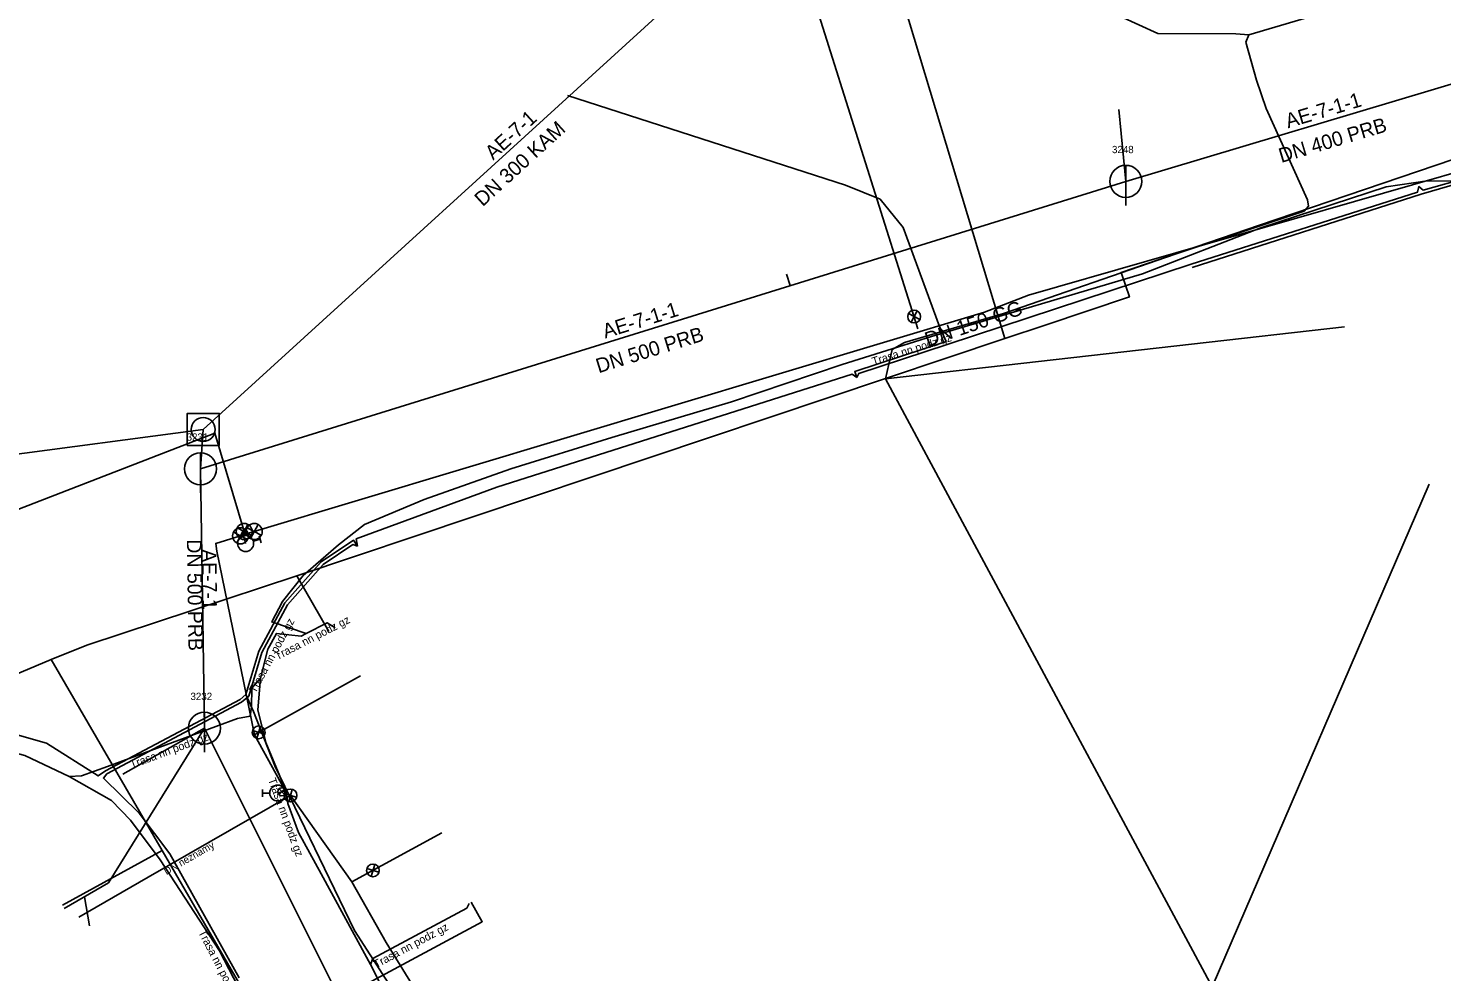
# Model space of a CAD drawing. Extents: x -493753 to -49291, y -1127285 to -112662.
# Drawn here: x -493312 to -493223.7, y -1127083.7 to -1127024.8 of the extents above; entities that cross this region are included whole.
import ezdxf

# ---------------------------------------------------------------- set-up
doc = ezdxf.new("R2010")
doc.units = 0
for name, color, linetype in [('Vrstva 1', 7, 'Continuous'), ('Vrstva 14', 7, 'Continuous'), ('Vrstva 15', 7, 'Continuous'), ('Vrstva 17', 7, 'Continuous'), ('Vrstva 19', 7, 'Continuous'), ('Vrstva 20', 7, 'Continuous'), ('Vrstva 22', 7, 'Continuous'), ('Vrstva 24', 7, 'Continuous'), ('Vrstva 25', 7, 'Continuous'), ('Vrstva 26', 7, 'Continuous'), ('Vrstva 28', 7, 'Continuous'), ('Vrstva 39', 7, 'Continuous'), ('Vrstva 5', 7, 'Continuous'), ('Vrstva 9', 7, 'Continuous')]:
    doc.layers.add(name, color=color, linetype=linetype)

# ---------------------------------------------------------------- blocks, each defined once
blk = doc.blocks.new('MOSYM1')
at = {"layer": 'Vrstva 1'}
blk.add_lwpolyline([(-0.05, -0.05), (0.05, -0.05), (0.05, 0.05), (-0.05, 0.05), (-0.05, -0.05)], dxfattribs=at)
blk.add_circle((0, 0), 0.0375, dxfattribs=at)
blk = doc.blocks.new('_UZAVE')
at = {"layer": 'Vrstva 1'}
for p, q in [((-0.035, -0.035), (0.035, 0.035)), ((0.035, -0.035), (-0.035, 0.035))]:
    blk.add_line(p, q, dxfattribs=at)
for radius in [0.05, 0.0025]:
    blk.add_circle((0, 0), radius, dxfattribs=at)
blk = doc.blocks.new('_UZAV0')
at = {"layer": 'Vrstva 1'}
for p, q in [((-0.035, -0.035), (0.035, 0.035)), ((0.035, -0.035), (-0.035, 0.035))]:
    blk.add_line(p, q, dxfattribs=at)
for radius in [0.05, 0.0025]:
    blk.add_circle((0, 0), radius, dxfattribs=at)
blk = doc.blocks.new('_HYDRA')
at = {"layer": 'Vrstva 1'}
for p, q in [((-0.0225, 0.095), (0.0225, 0.095)), ((0, 0.095), (0, 0.05))]:
    blk.add_line(p, q, dxfattribs=at)
blk.add_circle((0, 0), 0.05, dxfattribs=at)
blk = doc.blocks.new('_SACH0')
at = {"layer": 'Vrstva 1'}
blk.add_line((0, 0.05), (0, -0.075), dxfattribs=at)
blk.add_circle((0, 0), 0.05, dxfattribs=at)

msp = doc.modelspace()

# ---------------------------------------------------------------- linework, layer by layer
at = {"layer": 'Vrstva 1'}
for p, q in [((-493295.19, -1127058.95), (-493293.19, -1127062.42)), ((-493308.31, -1127063.27), (-493310.54, -1127064.17)), ((-493303.61, -1127076.09), (-493309.83, -1127079.5))]:
    msp.add_line(p, q, dxfattribs=at)
for points in [[(-493250.96, -1127044.13), (-493264.29, -1127000), (-493267.86, -1126988.17), (-493270.15, -1126981.69)], [(-493211.21, -1127031.6), (-493221.15, -1127034.33), (-493221.76, -1127032.53), (-493224.08, -1127033.32), (-493235.06, -1127037.06), (-493243.7, -1127040), (-493243.18, -1127041.53), (-493248.45, -1127043.29), (-493250.96, -1127044.13), (-493295.19, -1127058.95), (-493308.31, -1127063.27)], [(-493344.2, -1127078.27), (-493319.39, -1127067.89), (-493310.54, -1127064.17)], [(-493310.54, -1127064.17), (-493303.61, -1127076.09), (-493297.49, -1127086.65), (-493292.63, -1127095.05), (-493290.18, -1127099.28), (-493289.82, -1127099.92), (-493284.29, -1127109.66), (-493280.22, -1127116.82), (-493273.01, -1127129.21), (-493269.95, -1127134.48), (-493269.4, -1127135.43), (-493265.789, -1127142.323)], [(-493297.49, -1127086.65), (-493295.74, -1127087.06), (-493283.61, -1127080.54), (-493284.31, -1127079.33)]]:
    msp.add_lwpolyline(points, dxfattribs=at)
at = {"layer": 'Vrstva 14'}
for points in [[(-493258.41, -1127046.65), (-493229.74, -1127043.4)], [(-493238.01, -1127084.61), (-493258.41, -1127046.65)], [(-493238.01, -1127084.61), (-493224.45, -1127053.23)]]:
    msp.add_lwpolyline(points, dxfattribs=at)
at = {"layer": 'Vrstva 15'}
for p, q in [((-493301.04, -1127049.81), (-493263.8, -1127015.89)), ((-493215.87, -1127026.1), (-493243.41, -1127034.33)), ((-493243.84, -1127029.84), (-493243.41, -1127034.32)), ((-493243.41, -1127034.33), (-493301.21, -1127052.27)), ((-493264.61, -1127040.11), (-493264.38, -1127040.83)), ((-493332.87, -1127054), (-493301.04, -1127049.81)), ((-493301.21, -1127052.27), (-493301.04, -1127049.81)), ((-493300.97, -1127068.46), (-493301.21, -1127052.27)), ((-493306.06, -1127071.32), (-493300.97, -1127068.46)), ((-493280.38, -1127109.5), (-493300.97, -1127068.46)), ((-493308.14, -1127080.8), (-493308.46, -1127078.98))]:
    msp.add_line(p, q, dxfattribs=at)
msp.add_lwpolyline([(-493309.72, -1127079.71), (-493306.95, -1127078.11), (-493300.97, -1127068.46)], dxfattribs=at)
at = {"layer": 'Vrstva 20'}
for p, q in [((-493256.39, -1127043.53), (-493274.59, -1126985.82)), ((-493298.42, -1127056.37), (-493298.48, -1127056.18)), ((-493298.42, -1127056.37), (-493298.71, -1127056.45)), ((-493298.39, -1127056.93), (-493298.52, -1127056.4)), ((-493295.59, -1127072.66), (-493304.48, -1127077.77)), ((-493286.13, -1127075), (-493291.75, -1127078.05)), ((-493304.48, -1127077.77), (-493308.81, -1127080.25))]:
    msp.add_line(p, q, dxfattribs=at)
for points in [[(-493298.48, -1127056.18), (-493300.31, -1127050.04), (-493321.24, -1127058.14), (-493355.65, -1127071.3), (-493365, -1127074.9), (-493368.31, -1127076.35), (-493386.57, -1127054.09), (-493416.18, -1127013.57), (-493425.33, -1127000), (-493450.1, -1126961.95), (-493457.06, -1126948.64)], [(-493219.05, -1127032.65), (-493219.91, -1127032.94), (-493249.48, -1127041.42), (-493252.24, -1127042.48), (-493297.85, -1127056.18)], [(-493297.85, -1127056.18), (-493298.14, -1127056.27), (-493298.42, -1127056.37)], [(-493298.71, -1127056.45), (-493300.26, -1127056.92), (-493300.18, -1127057.4), (-493297.84, -1127068.87), (-493295.92, -1127072.34), (-493295.59, -1127072.66), (-493291.75, -1127078.05), (-493289.61, -1127081.83), (-493285.88, -1127087.87), (-493285.64, -1127088.31), (-493284.46, -1127091.33), (-493277.34, -1127105.5), (-493273.67, -1127111.53), (-493268.24, -1127121.11), (-493263.75, -1127129.69), (-493262.62, -1127131.58), (-493258.641, -1127138.619)], [(-493291.21, -1127065.2), (-493297.58, -1127068.72), (-493297.84, -1127068.87)], [(-493295.92, -1127072.34), (-493296.13, -1127072.43), (-493296.38, -1127072.51)]]:
    msp.add_lwpolyline(points, dxfattribs=at)
at = {"layer": 'Vrstva 25'}
for points in [[(-493260.22, -1127046.57), (-493260.34, -1127046.2), (-493254.63, -1127044.32), (-493255.05, -1127043.39), (-493257.32, -1127037.21), (-493258.76, -1127035.43), (-493260.92, -1127034.55), (-493278.28, -1127028.96)], [(-493260.22, -1127046.57), (-493260.09, -1127046.32), (-493254.57, -1127044.51), (-493239.33, -1127039.5), (-493225.18, -1127034.99), (-493225.11, -1127034.65), (-493224.84, -1127034.88), (-493222.03, -1127034.07), (-493217.89, -1127035.04), (-493215.41, -1127036.97), (-493213.7, -1127040.65), (-493212.86, -1127040.33), (-493206.46, -1127037.45), (-493205.76, -1127037.19), (-493205.83, -1127035.11), (-493205.49, -1127032.1), (-493204.16, -1127029.47), (-493203.78, -1127030.01)], [(-493203.78, -1127030.01), (-493204.09, -1127029.77), (-493205.29, -1127032.16), (-493205.63, -1127035.12), (-493205.56, -1127037.33), (-493206.38, -1127037.63), (-493212.78, -1127040.51), (-493213.8, -1127040.9), (-493215.57, -1127037.09), (-493217.97, -1127035.22), (-493222.03, -1127034.27), (-493224.95, -1127035.12), (-493239.27, -1127039.69)], [(-493260.22, -1127046.57), (-493260.5, -1127046.35), (-493282.7, -1127053.42), (-493291.48, -1127056.64), (-493291.4, -1127057.09)], [(-493291.4, -1127057.09), (-493291.65, -1127056.73), (-493293.68, -1127058.08), (-493295.94, -1127060.63), (-493297.56, -1127063.66), (-493298.37, -1127066.35), (-493298.73, -1127066.66), (-493307.14, -1127071.12), (-493307.61, -1127071.44), (-493310.84, -1127069.4), (-493314.8, -1127068.28), (-493317.63, -1127068.47), (-493317.86, -1127068.21)], [(-493298.8, -1127084.04), (-493303.13, -1127076.31), (-493305.04, -1127073.77), (-493307.27, -1127071.57), (-493307.06, -1127071.3), (-493298.65, -1127066.84), (-493298.19, -1127066.46), (-493297.37, -1127063.74), (-493295.77, -1127060.75), (-493293.55, -1127058.23), (-493291.7, -1127057), (-493291.4, -1127057.09)]]:
    msp.add_lwpolyline(points, dxfattribs=at)
at = {"layer": 'Vrstva 26'}
for p, q in [((-493298.37, -1127066.35), (-493297.89, -1127067.41)), ((-493297.89, -1127067.41), (-493296.57, -1127070.81)), ((-493296.57, -1127070.81), (-493291.59, -1127081.08)), ((-493291.59, -1127081.08), (-493288.11, -1127086.48))]:
    msp.add_line(p, q, dxfattribs=at)
at = {"layer": 'Vrstva 39'}
for points in [[(-493235.73, -1127025.17), (-493236.53, -1127025.12), (-493241.4, -1127025.09), (-493243.79, -1127024), (-493248.52, -1127013.69), (-493250.11, -1127006.96), (-493251.66, -1127001.72), (-493252.99, -1126995.77), (-493253.77, -1126987.81), (-493254.97, -1126977.02), (-493255.48, -1126962.33), (-493256.31, -1126954.12), (-493256.68, -1126945.15), (-493257.3, -1126943.45), (-493260.26, -1126941.69), (-493266.63, -1126938.06), (-493269.86, -1126938.09), (-493289.32, -1126944.6), (-493307.43, -1126950.45), (-493319.46, -1126954.73), (-493321.82, -1126955.73), (-493322.21, -1126955.38)], [(-493235.73, -1127025.17), (-493229.59, -1127023.36), (-493217.62, -1127019.87), (-493209.8, -1127017.48), (-493201.12, -1127014.06), (-493191.79, -1127010.53), (-493180.27, -1127008.11), (-493179.99, -1127008.93), (-493179.17, -1127010.93), (-493177.18, -1127016.55), (-493176.51, -1127018.4), (-493171.32, -1127029.71), (-493169.32, -1127034.4), (-493165.23, -1127043.1), (-493161.92, -1127050.08), (-493161.26, -1127050.88)], [(-493258.41, -1127046.65), (-493258, -1127044.82), (-493257.23, -1127044.38), (-493251.05, -1127042.58), (-493240.33, -1127038.87), (-493232.27, -1127036.18), (-493231.99, -1127035.87), (-493232.06, -1127035.48), (-493234.63, -1127029.78), (-493235.25, -1127028.01), (-493235.92, -1127025.62), (-493235.73, -1127025.17)]]:
    msp.add_lwpolyline(points, dxfattribs=at)
at = {"layer": 'Vrstva 5'}
for points in [[(-493294.6, -1127062.55), (-493296.76, -1127061.82), (-493296.08, -1127060.54), (-493294.79, -1127058.92), (-493292.58, -1127057.01), (-493290.97, -1127055.75), (-493287.24, -1127054.18), (-493281.83, -1127052.27), (-493275.52, -1127050.32), (-493268.05, -1127048.08), (-493261.13, -1127045.75), (-493255.54, -1127044), (-493242.37, -1127040.1), (-493234.97, -1127037.22), (-493227.14, -1127034.67), (-493224.59, -1127034.28), (-493222.11, -1127034.31), (-493219.35, -1127035.1), (-493217.51, -1127035.69), (-493216.02, -1127036.75), (-493214.15, -1127038.64), (-493213.79, -1127039.43), (-493213.44, -1127041.17)], [(-493294.6, -1127062.55), (-493293.29, -1127061.88), (-493292.8, -1127062.19)], [(-493294.6, -1127062.55), (-493294.93, -1127062.72), (-493296.47, -1127062.54), (-493297, -1127063.52), (-493297.46, -1127065.33)], [(-493297.46, -1127065.33), (-493298.01, -1127065.97), (-493298.03, -1127067.13), (-493298.11, -1127067.7), (-493298.89, -1127067.85), (-493307.03, -1127070.85), (-493308.65, -1127071.43), (-493309.42, -1127071.48)], [(-493290.59, -1127083.21), (-493290.84, -1127082.76), (-493293.67, -1127077.56), (-493295.09, -1127074.98), (-493295.76, -1127073.16), (-493295.88, -1127072.35), (-493297.13, -1127069.35), (-493297.63, -1127067.32), (-493297.46, -1127065.33)], [(-493309.42, -1127071.48), (-493312.18, -1127070.17), (-493314.91, -1127069.46), (-493317.14, -1127069.17), (-493318.88, -1127069.38), (-493323.79, -1127070.46), (-493330.76, -1127073.17), (-493334.55, -1127075.03), (-493338.89, -1127076.91), (-493343.3, -1127078.76), (-493344.09, -1127079.15), (-493345.41, -1127079.25)], [(-493291.68, -1127098.47), (-493292.92, -1127096.12), (-493296.27, -1127089.59), (-493300.03, -1127082.35), (-493303.74, -1127076.68), (-493305.59, -1127074.21), (-493306.76, -1127072.98), (-493309.42, -1127071.48)], [(-493290.59, -1127083.21), (-493290.44, -1127082.84), (-493284.58, -1127079.7), (-493284.42, -1127079.4)], [(-493284.76, -1127093.64), (-493284.99, -1127093.23), (-493288.82, -1127086.72), (-493290.59, -1127083.21)]]:
    msp.add_lwpolyline(points, dxfattribs=at)

# ---------------------------------------------------------------- block references
at = {"layer": 'Vrstva 17', "xscale": 19.997500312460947, "yscale": 19.997500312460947}
for p in [(-493243.41, -1127034.32), (-493301.21, -1127052.27), (-493300.97, -1127068.46)]:
    msp.add_blockref('_SACH0', p, dxfattribs=at)
at = {"layer": 'Vrstva 22'}
for name, p, xscale, yscale, rotation in [('_UZAV0', (-493256.63, -1127042.76), 7.999000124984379, 7.999000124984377, 107.498386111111), ('_UZAVE', (-493298.71, -1127056.45), 9.998750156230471, 9.998750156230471, 16.6527333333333), ('_UZAVE', (-493298.48, -1127056.18), 9.998750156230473, 9.998750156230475, -73.34982222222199), ('_HYDRA', (-493298.39, -1127056.93), 9.998750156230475, 9.998750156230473, -73.90719000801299), ('_UZAVE', (-493297.85, -1127056.18), 9.998750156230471, 9.998750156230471, 16.9785611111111), ('_UZAV0', (-493297.58, -1127068.72), 7.999000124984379, 7.999000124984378, -60.84847777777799), ('_HYDRA', (-493296.38, -1127072.51), 9.998750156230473, 9.998750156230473, 90), ('_UZAVE', (-493296.13, -1127072.43), 4.999375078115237, 4.999375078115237, 90), ('_UZAV0', (-493295.59, -1127072.66), 7.999000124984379, 7.999000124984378, -60.51158888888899), ('_UZAV0', (-493290.44, -1127077.34), 7.999000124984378, 7.999000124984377, 118.49952500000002)]:
    msp.add_blockref(name, p, dxfattribs=dict(at, xscale=xscale, yscale=yscale, rotation=rotation))
at = {"layer": 'Vrstva 28', "xscale": 19.997500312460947, "yscale": 19.997500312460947}
msp.add_blockref('MOSYM1', (-493301.04, -1127049.81), dxfattribs=at)

# ---------------------------------------------------------------- texts
at = {"layer": 'Vrstva 19'}
for s, rotation, p in [('AE-7-1-1', 16.63738, (-493233.277, -1127031.01)), ('DN 300 KAM', 42.32542, (-493283.585, -1127035.933)), ('AE-7-1', 42.32542, (-493282.929, -1127033.032)), ('DN 400 PRB', 16.63738, (-493233.697, -1127033.175)), ('AE-7-1-1', 17.24779, (-493275.928, -1127044.139)), ('DN 500 PRB', 17.24779, (-493276.344, -1127046.306)), ('DN 500 PRB', 270.85626, (-493302.064, -1127056.676)), ('AE-7-1', 270.85626, (-493301.133, -1127057.289))]:
    msp.add_text(s, height=0.9099, rotation=rotation, dxfattribs=at).set_placement(p)
for s, p in [('3248', (-493244.272, -1127032.56)), ('3231', (-493302.078, -1127050.51)), ('3232', (-493301.836, -1127066.7))]:
    msp.add_text(s, height=0.4549, dxfattribs=at).set_placement(p)
at = {"layer": 'Vrstva 24'}
for s, height, rotation, p in [('DN 150 GG', 0.9099, 18.89709, (-493255.779, -1127044.657)), ('DN neznámý', 0.455, 29.86143, (-493303.34, -1127077.635))]:
    msp.add_text(s, height=height, rotation=rotation, dxfattribs=at).set_placement(p)
at = {"layer": 'Vrstva 9'}
for rotation, p in [(17.3511, (-493259.174, -1127045.817)), (61.53729, (-493297.777, -1127066.31)), (27.24877, (-493296.411, -1127064.215)), (20.25226, (-493305.506, -1127070.986)), (290.09455, (-493296.998, -1127071.67)), (297.43577, (-493301.365, -1127081.205)), (28.12321, (-493290.233, -1127083.46))]:
    msp.add_text('Trasa nn podz gz', height=0.5, rotation=rotation, dxfattribs=at).set_placement(p)

doc.saveas('drawing.dxf')
